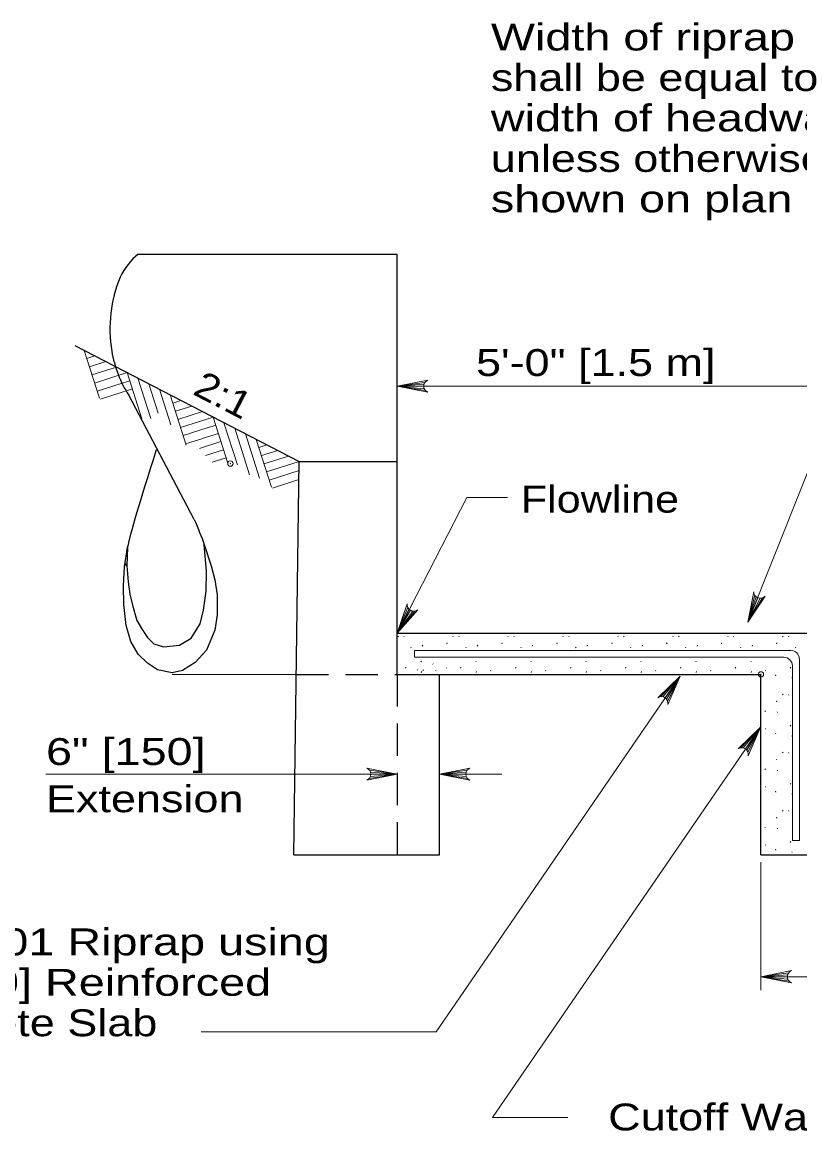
# Model space of a CAD drawing. Extents: x 685.4 to 719.4, y 1059.8 to 1105.8.
# Drawn here: x 702.97 to 707.48, y 1088.27 to 1094.7 of the extents above; entities that cross this region are included whole.
import ezdxf
from ezdxf.enums import TextEntityAlignment as Align

# ---------------------------------------------------------------- set-up
doc = ezdxf.new("R2010")
doc.units = 0
doc.header["$LTSCALE"] = 0.062
doc.header["$PDMODE"] = 32
doc.header["$PDSIZE"] = 0.031
doc.linetypes.add('MEDIUM_DASHED', pattern=[4.5, 3, -1.5])
doc.layers.add('1', color=7, linetype='Continuous', lineweight=13)

msp = doc.modelspace()

# ---------------------------------------------------------------- linework, layer by layer
at = {"layer": '1', "lineweight": 25}
for p, q in [((703.63742, 1093.3505), (705.141, 1093.35025)), ((704.64125, 1093.35025), (705.141, 1093.35025)), ((705.141, 1090.91292), (705.141, 1093.35025)), ((703.27142, 1092.81983), (704.57217, 1092.14725)), ((703.96342, 1091.81083), (703.58375, 1092.53225)), ((704.54125, 1089.867), (704.57217, 1092.14725)), ((704.57217, 1092.14725), (705.141, 1092.14725)), ((705.141, 1091.15183), (708.03575, 1091.15183)), ((703.836, 1090.91317), (704.55667, 1090.913)), ((705.141, 1090.913), (707.25, 1090.913)), ((705.38542, 1089.867), (705.38542, 1090.91292)), ((707.25, 1089.867), (707.25, 1090.913)), ((704.54125, 1089.867), (705.38542, 1089.867)), ((707.25, 1089.867), (707.65533, 1089.867))]:
    msp.add_line(p, q, dxfattribs=at)
at = {"layer": '1'}
for p, q in [((703.32533, 1092.792), (703.41375, 1092.51408)), ((703.34033, 1092.74475), (703.38767, 1092.75983)), ((703.35542, 1092.69742), (703.45, 1092.7275)), ((703.3705, 1092.65017), (703.51233, 1092.69525)), ((703.3855, 1092.60292), (703.57475, 1092.66308)), ((703.57475, 1092.66308), (703.65983, 1092.39558)), ((703.40058, 1092.55558), (703.54058, 1092.60017)), ((703.5425, 1092.60075), (703.58975, 1092.61583)), ((703.637, 1092.63092), (703.71133, 1092.39717)), ((703.69933, 1092.59867), (703.75392, 1092.42708)), ((705.30125, 1092.60675), (705.141, 1092.58433)), ((705.29583, 1092.59567), (705.141, 1092.58433)), ((705.29417, 1092.58433), (705.141, 1092.58433)), ((705.297, 1092.56992), (705.141, 1092.58433)), ((705.30308, 1092.5595), (705.141, 1092.58433)), ((703.4195, 1092.50942), (703.50825, 1092.53767)), ((703.51017, 1092.53833), (703.60475, 1092.56842)), ((703.76175, 1092.56633), (703.827, 1092.36133)), ((703.824, 1092.53408), (703.91717, 1092.24167)), ((703.83908, 1092.48692), (703.88633, 1092.50192)), ((703.85417, 1092.4395), (703.94875, 1092.46958)), ((703.86925, 1092.39217), (704.01108, 1092.43742)), ((703.88425, 1092.345), (704.07342, 1092.40517)), ((704.07342, 1092.40517), (704.1585, 1092.13767)), ((703.89933, 1092.29775), (704.03933, 1092.34225)), ((704.04117, 1092.34292), (704.0885, 1092.35792)), ((704.13567, 1092.37292), (704.21392, 1092.12742)), ((704.198, 1092.34075), (704.284, 1092.07083)), ((703.91833, 1092.25158), (704.007, 1092.27983)), ((703.99325, 1092.22333), (704.11858, 1092.26325)), ((704.00892, 1092.28042), (704.10358, 1092.31058)), ((704.2605, 1092.30842), (704.34233, 1092.05133)), ((704.32275, 1092.27617), (704.41125, 1091.99833)), ((704.02942, 1092.18292), (704.13358, 1092.21608)), ((704.33783, 1092.22892), (704.38508, 1092.244)), ((704.35292, 1092.18158), (704.44758, 1092.21175)), ((704.06825, 1092.14308), (704.14867, 1092.16875)), ((704.36792, 1092.13433), (704.50983, 1092.1795)), ((704.383, 1092.087), (704.57217, 1092.14725)), ((704.398, 1092.03983), (704.5715, 1092.095)), ((704.417, 1091.99367), (704.57075, 1092.04258)), ((705.141, 1091.15183), (705.54533, 1091.93983)), ((705.54533, 1091.93983), (705.77975, 1091.93983)), ((703.57533, 1091.60783), (703.57158, 1091.61233)), ((704.0235, 1091.6605), (704.02167, 1091.6625)), ((704.03008, 1091.64042), (704.02292, 1091.649)), ((703.5725, 1091.54), (703.56183, 1091.55258)), ((703.57233, 1091.54492), (703.56242, 1091.55667)), ((707.21367, 1091.37217), (707.17475, 1091.21517)), ((707.222, 1091.36292), (707.17475, 1091.21517)), ((707.23183, 1091.35725), (707.17475, 1091.21517)), ((707.25817, 1091.35633), (707.17475, 1091.21517)), ((707.24625, 1091.3545), (707.17475, 1091.21517)), ((705.20125, 1091.302), (705.141, 1091.15183)), ((705.20817, 1091.29175), (705.141, 1091.15183)), ((705.21717, 1091.28467), (705.141, 1091.15183)), ((705.24317, 1091.28008), (705.141, 1091.15183)), ((705.23108, 1091.27992), (705.141, 1091.15183)), ((705.14483, 1091.13508), (705.14725, 1091.1315)), ((705.179, 1091.13375), (705.18142, 1091.13017)), ((705.42817, 1091.09067), (705.43058, 1091.09608)), ((705.46358, 1091.13508), (705.466, 1091.1315)), ((705.49767, 1091.13375), (705.50008, 1091.13017)), ((705.74692, 1091.09067), (705.74933, 1091.09608)), ((705.78225, 1091.13508), (705.78467, 1091.1315)), ((705.81642, 1091.13375), (705.81883, 1091.13017)), ((706.06567, 1091.09067), (706.06808, 1091.09608)), ((706.101, 1091.13508), (706.10333, 1091.1315)), ((706.13508, 1091.13375), (706.1375, 1091.13017)), ((706.38442, 1091.09067), (706.38675, 1091.09608)), ((706.41975, 1091.13508), (706.42208, 1091.1315)), ((706.45383, 1091.13375), (706.45617, 1091.13017)), ((706.70308, 1091.09067), (706.7055, 1091.09608)), ((706.73842, 1091.13508), (706.74083, 1091.1315)), ((706.77258, 1091.13375), (706.775, 1091.13017)), ((707.02175, 1091.09067), (707.02417, 1091.09608)), ((707.05717, 1091.13508), (707.05958, 1091.1315)), ((707.09125, 1091.13375), (707.09367, 1091.13017)), ((707.3405, 1091.09067), (707.34292, 1091.09608)), ((707.37583, 1091.13508), (707.37825, 1091.1315)), ((707.41, 1091.13375), (707.41242, 1091.13017)), ((705.21917, 1091.06983), (705.2215, 1091.06625)), ((707.42267, 1091.05233), (705.24142, 1091.05233)), ((705.24142, 1091.05233), (705.24142, 1091.01242)), ((705.28625, 1091.07692), (705.28858, 1091.08225)), ((705.53792, 1091.06983), (705.54025, 1091.06625)), ((705.60492, 1091.07692), (705.60733, 1091.08225)), ((705.85658, 1091.06983), (705.859, 1091.06625)), ((705.92358, 1091.07692), (705.926, 1091.08225)), ((706.17533, 1091.06983), (706.17775, 1091.06625)), ((706.24242, 1091.07692), (706.24483, 1091.08225)), ((706.494, 1091.06983), (706.49642, 1091.06625)), ((706.56108, 1091.07692), (706.5635, 1091.08225)), ((706.81275, 1091.06983), (706.81508, 1091.06625)), ((706.87983, 1091.07692), (706.88217, 1091.08225)), ((707.13142, 1091.06983), (707.13383, 1091.06625)), ((707.1985, 1091.07692), (707.20092, 1091.08225)), ((707.45017, 1091.06983), (707.45258, 1091.06625)), ((707.38267, 1091.01242), (705.24142, 1091.01242)), ((705.27825, 1090.98958), (705.28067, 1090.98592)), ((705.34708, 1090.97475), (705.3495, 1090.97117)), ((705.59692, 1090.98958), (705.59933, 1090.98592)), ((705.91567, 1090.98958), (705.91808, 1090.98592)), ((706.23442, 1090.98958), (706.23683, 1090.98592)), ((706.55317, 1090.98958), (706.5555, 1090.98592)), ((706.87183, 1090.98958), (706.87425, 1090.98592)), ((707.1905, 1090.98958), (707.19292, 1090.98592)), ((707.47267, 1091.00242), (707.47267, 1089.94958)), ((705.18908, 1090.94925), (705.1915, 1090.95467)), ((705.25567, 1090.941), (705.25808, 1090.93742)), ((705.28025, 1090.92475), (705.28267, 1090.93008)), ((705.28983, 1090.93967), (705.29225, 1090.93608)), ((705.36333, 1090.93633), (705.36575, 1090.93275)), ((705.42367, 1090.95242), (705.42608, 1090.94883)), ((705.50792, 1090.94925), (705.51033, 1090.95467)), ((705.59892, 1090.92475), (705.60133, 1090.93008)), ((705.68208, 1090.93633), (705.6845, 1090.93275)), ((705.82658, 1090.94925), (705.829, 1090.95467)), ((705.91767, 1090.92475), (705.92, 1090.93008)), ((706.00083, 1090.93633), (706.00317, 1090.93275)), ((706.14533, 1090.94925), (706.14767, 1090.95467)), ((706.23642, 1090.92475), (706.23883, 1090.93008)), ((706.3195, 1090.93633), (706.32192, 1090.93275)), ((706.464, 1090.94925), (706.46642, 1090.95467)), ((706.55508, 1090.92475), (706.5575, 1090.93008)), ((706.63817, 1090.93633), (706.64058, 1090.93275)), ((706.66883, 1090.78375), (706.7815, 1090.90292)), ((706.68092, 1090.78283), (706.7815, 1090.90292)), ((706.69433, 1090.777), (706.7815, 1090.90292)), ((706.70267, 1090.76917), (706.7815, 1090.90292)), ((706.70875, 1090.75842), (706.7815, 1090.90292)), ((706.78267, 1090.94925), (706.78508, 1090.95467)), ((706.87383, 1090.92475), (706.87625, 1090.93008)), ((706.957, 1090.93633), (706.95933, 1090.93275)), ((707.1015, 1090.94925), (707.10392, 1090.95467)), ((707.1925, 1090.92475), (707.19492, 1090.93008)), ((707.27567, 1090.93633), (707.27808, 1090.93275)), ((707.33492, 1090.90975), (707.3355, 1090.90433)), ((707.42017, 1090.94925), (707.42258, 1090.95467)), ((707.43267, 1090.96242), (707.43267, 1089.94958)), ((707.42892, 1090.89383), (707.43133, 1090.89025)), ((707.37583, 1090.798), (707.37825, 1090.79442)), ((707.41, 1090.79667), (707.41242, 1090.793)), ((707.3405, 1090.75367), (707.34292, 1090.75908)), ((707.27342, 1090.7015), (707.27583, 1090.69792)), ((707.34417, 1090.695), (707.34658, 1090.69142)), ((707.13425, 1090.48758), (707.24708, 1090.60658)), ((707.14625, 1090.48667), (707.24708, 1090.60658)), ((707.15975, 1090.48083), (707.24708, 1090.60658)), ((707.16808, 1090.473), (707.24708, 1090.60658)), ((707.17408, 1090.46225), (707.24708, 1090.60658)), ((707.27567, 1090.59933), (707.27808, 1090.59575)), ((707.42017, 1090.61225), (707.42258, 1090.61767)), ((707.33492, 1090.57267), (707.3355, 1090.56725)), ((707.42892, 1090.55675), (707.43133, 1090.55317)), ((707.37583, 1090.461), (707.37825, 1090.45742)), ((707.41, 1090.45958), (707.41242, 1090.456)), ((707.3405, 1090.41658), (707.34292, 1090.42192)), ((703.10358, 1090.334), (705.14092, 1090.334)), ((704.97875, 1090.30917), (705.14092, 1090.334)), ((704.98067, 1090.35642), (705.14092, 1090.334)), ((704.98492, 1090.31958), (705.14092, 1090.334)), ((704.98608, 1090.34525), (705.14092, 1090.334)), ((704.98775, 1090.334), (705.14092, 1090.334)), ((705.54567, 1090.35642), (705.38542, 1090.334)), ((705.54025, 1090.34525), (705.38542, 1090.334)), ((705.53858, 1090.334), (705.38542, 1090.334)), ((705.54142, 1090.31958), (705.38542, 1090.334)), ((705.54758, 1090.30917), (705.38542, 1090.334)), ((705.38542, 1090.334), (705.74767, 1090.334)), ((707.27342, 1090.36442), (707.27583, 1090.36083)), ((707.34417, 1090.35792), (707.34658, 1090.35433)), ((707.27567, 1090.26225), (707.27808, 1090.25858)), ((707.42017, 1090.27517), (707.42258, 1090.28058)), ((707.33492, 1090.23558), (707.3355, 1090.23017)), ((707.42892, 1090.21967), (707.43133, 1090.21608)), ((707.3405, 1090.07942), (707.34292, 1090.08483)), ((707.37583, 1090.12392), (707.37825, 1090.12033)), ((707.41, 1090.1225), (707.41242, 1090.11892)), ((707.27342, 1090.02742), (707.27583, 1090.02383)), ((707.34417, 1090.02092), (707.34658, 1090.01733)), ((707.42017, 1089.93808), (707.42258, 1089.9435)), ((707.43267, 1089.94958), (707.47267, 1089.94958)), ((707.27567, 1089.92508), (707.27808, 1089.9215)), ((707.33492, 1089.8985), (707.3355, 1089.89317)), ((707.42892, 1089.88267), (707.43133, 1089.879)), ((707.25, 1089.82275), (707.25, 1089.08033)), ((707.41025, 1089.18142), (707.25, 1089.159)), ((707.40483, 1089.17033), (707.25, 1089.159)), ((707.40317, 1089.159), (707.25, 1089.159)), ((707.406, 1089.14458), (707.25, 1089.159)), ((707.41208, 1089.13417), (707.25, 1089.159)), ((707.25, 1089.159), (709.06117, 1089.159))]:
    msp.add_line(p, q, dxfattribs=at)
at = {"layer": '1', "linetype": 'MEDIUM_DASHED', "lineweight": 25}
for p, q in [((704.55542, 1090.91292), (705.141, 1090.91292)), ((705.14092, 1090.913), (705.14092, 1089.867))]:
    msp.add_line(p, q, dxfattribs=at)
at = {"layer": '1'}
for points in [[(707.17475, 1091.21517), (708.1295, 1093.60858), (707.79417, 1093.60858)], [(705.318, 1092.54892), (705.141, 1092.58433), (705.318, 1092.61975)], [(705.141, 1092.58433), (706.7035, 1092.58433), (707.65533, 1092.58433)], [(707.27358, 1091.36625), (707.17475, 1091.21517), (707.20783, 1091.39258)], [(705.25975, 1091.28775), (705.141, 1091.15183), (705.19833, 1091.32292)], [(706.7815, 1090.90292), (705.36567, 1088.83983), (704.00308, 1088.83983)], [(706.65167, 1090.7775), (706.7815, 1090.90292), (706.70983, 1090.73725)], [(707.25, 1090.60958), (705.694, 1088.34217), (706.13017, 1088.34217)], [(707.11708, 1090.48142), (707.24708, 1090.60658), (707.17517, 1090.44108)], [(704.96392, 1090.29858), (705.14092, 1090.334), (704.96392, 1090.36933)], [(705.56242, 1090.29858), (705.38542, 1090.334), (705.56242, 1090.36933)], [(707.427, 1089.12358), (707.25, 1089.159), (707.427, 1089.19442)]]:
    msp.add_lwpolyline(points, dxfattribs=at)
at = {"layer": '1', "lineweight": 25}
for points in [[(704.02133, 1091.66708), (704.06258, 1091.5425), (704.08317, 1091.46133), (704.09617, 1091.37425), (704.09583, 1091.25758), (704.0825, 1091.16883), (704.03433, 1091.05342), (703.96875, 1090.98142), (703.89575, 1090.93608), (703.83608, 1090.92117), (703.75083, 1090.93933), (703.692, 1090.97783), (703.6375, 1091.03042), (703.59642, 1091.10408), (703.56917, 1091.19708), (703.55567, 1091.31767), (703.55283, 1091.42592), (703.55917, 1091.53658), (703.57733, 1091.64808)], [(703.57733, 1091.64808), (703.57217, 1091.543), (703.58, 1091.44975), (703.58942, 1091.37833), (703.60492, 1091.31425), (703.63125, 1091.22633), (703.66092, 1091.17325), (703.692, 1091.12742), (703.7295, 1091.09083), (703.78542, 1091.0725), (703.87875, 1091.08158), (703.94583, 1091.12383), (703.99858, 1091.20608), (704.01742, 1091.28492), (704.03292, 1091.3965), (704.0345, 1091.51192), (704.02133, 1091.66708)]]:
    msp.add_lwpolyline(points, dxfattribs=at)
at = {"layer": '1'}
for centre, start, end in [((705.33227, 1092.58435), 112.08782, 247.91395), ((707.24608, 1091.39267), 180.20734, 316.03346), ((705.23615, 1091.31776), 172.24034, 308.06647), ((706.67266, 1090.74562), 347.40685, 123.23297), ((707.13799, 1090.44948), 347.29659, 123.12272), ((704.94959, 1090.334), 292.08605, 67.91218), ((705.57673, 1090.334), 112.08782, 247.91395), ((707.44128, 1089.15902), 112.08782, 247.91395)]:
    msp.add_arc(centre, 0.0382, start, end, dxfattribs=at)
at = {"layer": '1', "lineweight": 25}
for centre, major_axis, start_param, end_param in [((703.83613, 1093.01505), (0, 0.40878), 0.608535, 1.0523476), ((704.05051, 1092.91709), (0, -0.67756), 4.2528342, 4.9042115), ((703.99557, 1092.90652), (0, -0.61216), 4.9073919, 5.370128)]:
    msp.add_ellipse(centre, major_axis=major_axis, ratio=0.850089, start_param=start_param, end_param=end_param, dxfattribs=at)
at = {"layer": '1'}
for centre in [(707.42266, 1091.00241), (707.38267, 1090.96243)]:
    msp.add_ellipse(centre, major_axis=(0.04998, 0), ratio=0.999895, start_param=6.2831853, end_param=7.8539816, dxfattribs=at)
at = {"layer": '1', "lineweight": 25}
for points in [[(703.57733, 1091.64808), (703.59858, 1091.74517), (703.6435, 1091.90092), (703.74483, 1092.2175)], [(703.96342, 1091.81083), (703.98617, 1091.75792), (704.00533, 1091.71008), (704.02133, 1091.66708)]]:
    msp.add_open_spline(points, degree=3, dxfattribs=at)
at = {"layer": '1'}
for p in [(704.173, 1092.13583), (707.25, 1090.913)]:
    msp.add_point(p, dxfattribs=at)

# ---------------------------------------------------------------- texts
for s, width, p in [('Width of riprap', 1.3, (705.68375, 1094.53167)), ('shall be equal to', 1.25, (705.68375, 1094.297)), ('width of headwall', 1.3, (705.68375, 1094.06233)), ('unless otherwise', 1.25, (705.68375, 1093.82767)), ('shown on plan', 1.3, (705.68375, 1093.593)), ('5\'-0" [1.5 m]', 1.25, (705.59767, 1092.64358)), ('Flowline', 1.2, (705.85692, 1091.851)), ('6" [150]', 1.3, (703.10383, 1090.38725)), ('Extension', 1.25, (703.10383, 1090.11325)), ('Item 601 Riprap using', 1.3, (702.09692, 1089.28325)), ('6" [150] Reinforced', 1.3, (702.09692, 1089.04858)), ('Concrete Slab', 1.25, (702.09692, 1088.81392))]:
    msp.add_text(s, height=0.156, dxfattribs=dict(at, width=width)).set_placement(p)
at = {"layer": '1', "width": 1.15}
msp.add_text('2:1', height=0.156, rotation=332.655, dxfattribs=at).set_placement((703.94808, 1092.54083))
at = {"layer": '1', "width": 1.25}
msp.add_text('Cutoff Wall', height=0.156, dxfattribs=at).set_placement((707.00162, 1088.2675), align=Align.CENTER)

doc.saveas('drawing.dxf')
